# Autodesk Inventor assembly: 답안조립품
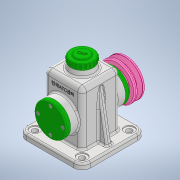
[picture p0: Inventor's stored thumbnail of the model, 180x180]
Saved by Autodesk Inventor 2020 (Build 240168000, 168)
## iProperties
Created: 2021-07
Part Number: 답안조립품
Document SubType Name: Assembly
Designer: Owner
Author: Owner
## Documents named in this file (14)
- C:\Users\Owner\Desktop\710715V1005\답안조립품.iam
- C:\Users\Owner\Desktop\710715V1005\본체.ipt
- C:\Users\Owner\Desktop\710715V1005\V-벨트풀리.ipt
- C:\Users\Owner\Desktop\710715V1005\뒤커버.ipt
- C:\Users\Owner\Desktop\710715V1005\멈춤링 15 x 1.ipt
- C:\Users\Owner\Desktop\710715V1005\베어링 15 x 35 x 11.ipt
- C:\Users\Owner\Desktop\710715V1005\볼트 M4 x 10.ipt
- C:\Users\Owner\Desktop\710715V1005\볼트 M6 x 12.ipt
- C:\Users\Owner\Desktop\710715V1005\상부캡.ipt
- C:\Users\Owner\Desktop\710715V1005\앞커버.ipt
- C:\Users\Owner\Desktop\710715V1005\오일실 15 25 7.ipt
- C:\Users\Owner\Desktop\710715V1005\와셔.ipt
- C:\Users\Owner\Desktop\710715V1005\축.ipt
- C:\Users\Owner\Desktop\710715V1005\키 5 x 5 x 14.ipt
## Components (1 placed, 1 different names)
1. V-벨트풀리:1
